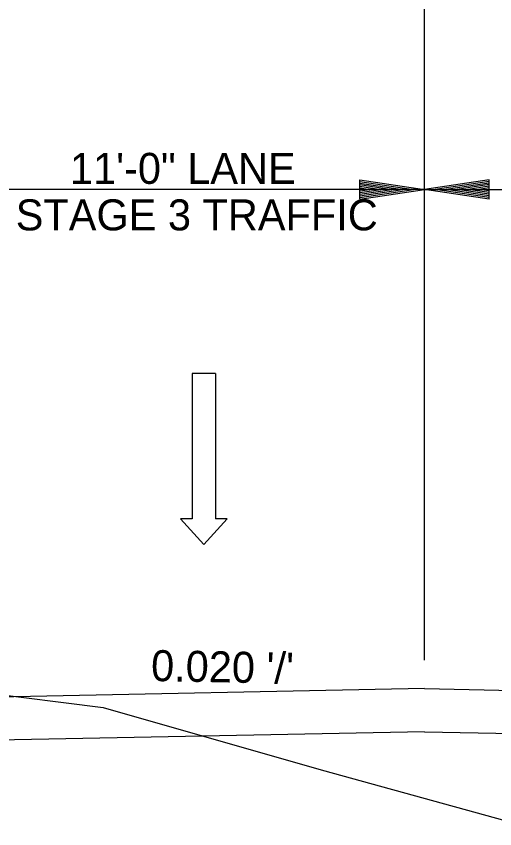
# Model space of a CAD drawing. Extents: x 1807779 to 1818251, y 673292 to 678849.
# Drawn here: x 1813494.7 to 1813605.8, y 676562.6 to 676751.3 of the extents above; entities that cross this region are included whole.
import ezdxf

# ---------------------------------------------------------------- set-up
doc = ezdxf.new("R2010")
doc.units = 0
for name, color, linetype in [('Dimensions', 7, 'Continuous'), ('EX_DRIVEWAY', 7, 'Continuous'), ('EX_TERRAIN', 7, 'Continuous')]:
    doc.layers.add(name, color=color, linetype=linetype)

msp = doc.modelspace()

# ---------------------------------------------------------------- linework, layer by layer
at = {"layer": 'Dimensions'}
for p, q in [((1813589.43, 676601.76), (1813589.43, 676764.5)), ((1813574.43, 676713.33), (1813589.43, 676711.08)), ((1813574.43, 676708.83), (1813574.43, 676713.33)), ((1813574.43, 676712.95), (1813586.93, 676711.08)), ((1813574.43, 676712.57), (1813584.35, 676711.08)), ((1813574.43, 676712.19), (1813581.85, 676711.08)), ((1813604.43, 676713.33), (1813589.43, 676711.08)), ((1813604.43, 676712.95), (1813591.94, 676711.08)), ((1813604.43, 676712.57), (1813594.52, 676711.08)), ((1813604.43, 676712.19), (1813597.01, 676711.08)), ((1813604.43, 676708.83), (1813604.43, 676713.33)), ((1813589.43, 676711.08), (1813479.43, 676711.08)), ((1813589.43, 676711.08), (1813530.01, 676711.08)), ((1813574.43, 676711.81), (1813579.31, 676711.08)), ((1813574.43, 676711.43), (1813576.8, 676711.08)), ((1813574.43, 676708.83), (1813589.43, 676711.08)), ((1813574.43, 676710.35), (1813579.31, 676711.08)), ((1813574.43, 676709.58), (1813584.35, 676711.08)), ((1813574.43, 676709.2), (1813586.93, 676711.08)), ((1813574.43, 676709.96), (1813581.85, 676711.08)), ((1813574.43, 676710.72), (1813576.8, 676711.08)), ((1813589.43, 676711.08), (1813648.86, 676711.08)), ((1813589.43, 676711.08), (1813699.43, 676711.08)), ((1813604.43, 676708.83), (1813589.43, 676711.08)), ((1813604.43, 676709.2), (1813591.94, 676711.08)), ((1813604.43, 676709.58), (1813594.52, 676711.08)), ((1813604.43, 676709.96), (1813597.01, 676711.08)), ((1813604.43, 676711.81), (1813599.56, 676711.08)), ((1813604.43, 676710.35), (1813599.56, 676711.08)), ((1813604.43, 676711.43), (1813602.06, 676711.08)), ((1813604.43, 676710.72), (1813602.06, 676711.08)), ((1813540.94, 676668.31), (1813540.94, 676634.59))]:
    msp.add_line(p, q, dxfattribs=at)
msp.add_lwpolyline([(1813540.94, 676668.31), (1813535.54, 676668.31), (1813535.54, 676634.59), (1813532.84, 676634.59), (1813538.24, 676628.67), (1813543.64, 676634.59), (1813540.94, 676634.59)], dxfattribs=at)
at = {"layer": 'EX_DRIVEWAY'}
for p, q in [((1813589.43, 676595.18), (1813479.45, 676592.98)), ((1813589.43, 676595.18), (1813699.41, 676592.98)), ((1813589.43, 676585.18), (1813479.45, 676582.98)), ((1813589.43, 676585.18), (1813802.36, 676580.92))]:
    msp.add_line(p, q, dxfattribs=at)
at = {"layer": 'EX_TERRAIN'}
msp.add_lwpolyline([(1812677.73, 676590.75), (1812733.39, 676557.8), (1812876.78, 676502.56), (1812958.07, 676504.7), (1813052.65, 676556.13), (1813143.36, 676593.92), (1813217.94, 676596.07), (1813298.12, 676597.14), (1813458.11, 676595), (1813486.58, 676594.36), (1813514.91, 676590.77), (1813565.47, 676576.34), (1813612.93, 676563.25), (1813727.64, 676502.24), (1813805.09, 676484.4), (1813860.58, 676479.74), (1813917.03, 676474.91), (1814103.84, 676473.94), (1814245.64, 676472.02)], dxfattribs=at)

# ---------------------------------------------------------------- texts
at = {"layer": 'Dimensions'}
for s, p in [('11\'-0" LANE', (1813507.21, 676712.37)), ('STAGE 3 TRAFFIC', (1813494.62, 676701.57))]:
    msp.add_text(s, height=7.2, dxfattribs=at).set_placement(p)
msp.add_text("0.020 '/'", height=7.2, rotation=358.8777, dxfattribs=at).set_placement((1813525.97, 676596.95))

doc.saveas('drawing.dxf')
